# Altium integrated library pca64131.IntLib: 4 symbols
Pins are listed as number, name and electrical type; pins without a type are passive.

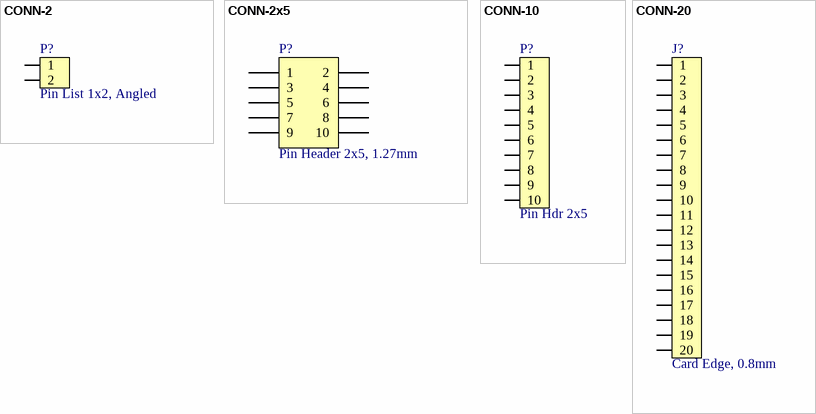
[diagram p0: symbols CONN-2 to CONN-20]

## CONN-2
designator P?, comment Pin List 1x2, Angled
Pin List 1x2, 2.54mm (100mil), Right Angled, SMD; Part Number: Pin List Ang 1x2 SMD, 2.54mm; Manufacturer: W-CON; Manufacturer Part Number: 1125B-1102S0Z135R2; Part number IPS: N.A.; Artikkelnr Noca: 55010023
footprint LIST_ANG_1x2-SMD-2.54MM
pins: 1, 2

## CONN-2x5
designator P?, comment Pin Header 2x5, 1.27mm
Pin Header 2x5, 1.27mm (50mil), SMD, Keying Shroud; Part Number: Pin Header 2x5 SMD, 1.27mm, KS; Manufacturer: W-CON; Manufacturer Part Number: 3132-10MS0BK00R1; Part number IPS: N.A.; Artikkelnr Noca: 55010009
footprint HDR_2x5-SMD-1.27mm-K
pins: 1, 2, 3, 4, 5, 6, 7, 8, 9, 10

## CONN-10
designator P?, comment Pin Hdr 2x5
Pin Header 2x5, 2.54mm (100mil) SMD; Part Number: Pin Header 2x5 SMD; Manufacturer: Molex; Part number IPS: N.A.; Artikkelnr Noca: 55019194
footprint HDR_2x5-SMD
pins: 1, 2, 3, 4, 5, 6, 7, 8, 9, 10

## CONN-20
designator J?, comment Card Edge, 0.8mm
0.8mm pitch, dual edge, card edge connector; Part Number: 10056847-101LF Mating Board; Artikkelnr Noca: N.A.
footprint 10056847-101LF Mating Board
pins: 1, 2, 3, 4, 5, 6, 7, 8, 9, 10, 11, 12, 13, 14, 15, 16, 17, 18, 19, 20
